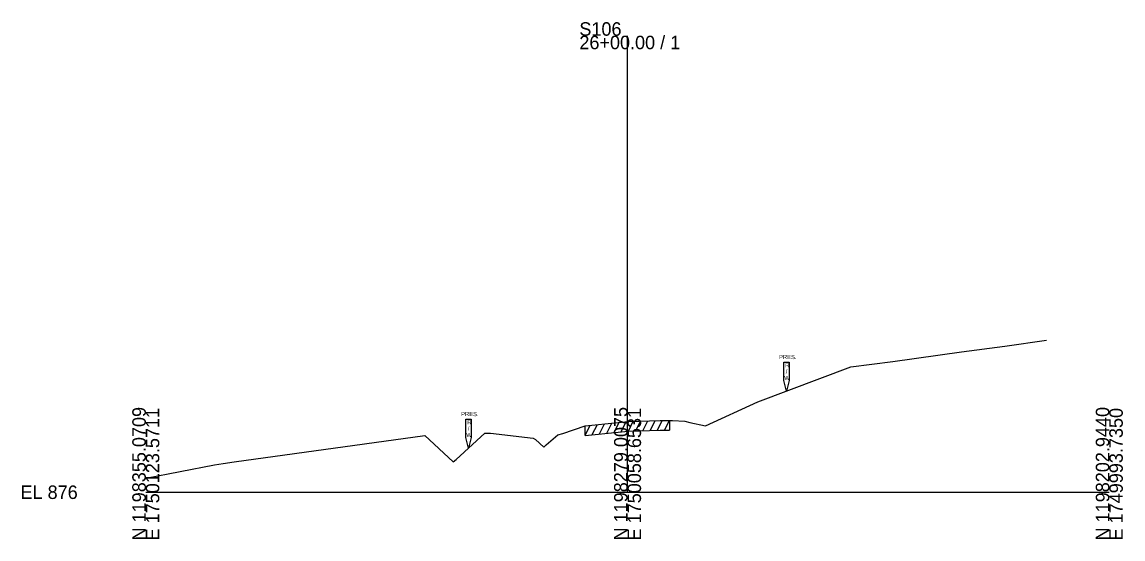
# Model space of a CAD drawing. Extents: x -26 to 1203, y -10 to 19527.
# Drawn here: x -25.7 to 202.8, y 1990.3 to 2097.5 of the extents above; entities that cross this region are included whole.
import ezdxf

# ---------------------------------------------------------------- set-up
doc = ezdxf.new("R2010")
doc.units = 0
for name, color, linetype in [('RD_GPK_XS_Cell', 7, 'Continuous'), ('RD_XS_ExGround', 7, 'Continuous'), ('RD_XS_ExPaveRet', 7, 'Continuous'), ('RD_XS_ExRW', 7, 'Continuous'), ('RD_XS_TX_Elev_EX', 7, 'Continuous')]:
    doc.layers.add(name, color=color, linetype=linetype)

msp = doc.modelspace()

# ---------------------------------------------------------------- linework, layer by layer
at = {"layer": 'RD_GPK_XS_Cell'}
for p, q in [((100, 2000), (100, 2094.69)), ((0, 2000), (100, 2000)), ((100, 2000), (200, 2000))]:
    msp.add_line(p, q, dxfattribs=at)
at = {"layer": 'RD_XS_ExGround'}
msp.add_lwpolyline([(0, 2002.9), (14.26, 2005.71), (16.03, 2005.96), (18.31, 2006.28), (57.95, 2011.78), (63.82, 2006.33), (64.43, 2006.79), (70.4, 2012.25), (71.57, 2012.23), (80.43, 2011.23), (80.9, 2010.91), (82.64, 2009.38), (83.14, 2009.83), (85.53, 2011.9), (86.54, 2012.2), (91.19, 2013.8), (98.06, 2014.49), (100.12, 2014.68), (106.74, 2014.86), (108.73, 2014.9), (109.33, 2014.87), (111.9, 2014.73), (112.95, 2014.47), (116.18, 2013.8), (127.04, 2018.72), (146.38, 2026.01), (155.1, 2027.13), (169.33, 2029.15), (178.32, 2030.3), (186.97, 2031.56)], dxfattribs=at)
at = {"layer": 'RD_XS_ExPaveRet'}
for p, q in [((91.19, 2011.8), (92.24, 2013.9)), ((91.19, 2011.8), (91.19, 2013.8)), ((92.69, 2011.95), (93.74, 2014.06)), ((94.19, 2012.1), (95.24, 2014.21)), ((95.69, 2012.25), (96.74, 2014.36)), ((97.19, 2012.41), (98.24, 2014.51)), ((98.69, 2012.55), (99.74, 2014.65)), ((100.19, 2012.68), (101.2, 2014.71)), ((101.69, 2012.73), (102.7, 2014.75)), ((103.19, 2012.77), (104.2, 2014.79)), ((104.69, 2012.81), (105.7, 2014.83)), ((106.19, 2012.85), (107.2, 2014.87)), ((107.69, 2012.88), (108.7, 2014.9)), ((108.73, 2014.9), (108.73, 2012.9)), ((91.19, 2011.8), (98.06, 2012.49)), ((98.06, 2012.49), (100.12, 2012.68)), ((100.12, 2012.68), (106.74, 2012.86)), ((106.74, 2012.86), (108.73, 2012.9))]:
    msp.add_line(p, q, dxfattribs=at)
at = {"layer": 'RD_XS_ExRW'}
for points in [[(132.45, 2026.98), (133.55, 2026.98), (133.55, 2023.15), (133, 2020.97), (132.45, 2023.15)], [(66.45, 2015.15), (67.55, 2015.15), (67.55, 2011.32), (67, 2009.14), (66.45, 2011.32)]]:
    msp.add_lwpolyline(points, close=True, dxfattribs=at)

# ---------------------------------------------------------------- texts
at = {"layer": 'RD_GPK_XS_Cell'}
for s, p in [('S106', (90, 2094.69)), ('26+00.00 / 1', (90, 2091.89)), ('EL 876', (-26, 1998.6))]:
    msp.add_text(s, height=2.8, dxfattribs=at).set_placement(p)
for s, p in [('N 1198355.0709', (0, 1990)), ('E 1750123.5711', (2.8, 1990)), ('N 1198279.0075', (100, 1990)), ('E 1750058.6531', (102.8, 1990)), ('N 1198202.9440', (200, 1990)), ('E 1749993.7350', (202.8, 1990))]:
    msp.add_text(s, height=2.8, rotation=90, dxfattribs=at).set_placement(p)
at = {"layer": 'RD_XS_ExRW'}
for s, p in [('PRES.', (131.45, 2027.61)), ('R', (132.71, 2025.89)), ('/', (132.83, 2024.58)), ('W', (132.53, 2023.27)), ('PRES.', (65.45, 2015.78)), ('R', (66.71, 2014.06)), ('/', (66.83, 2012.75)), ('W', (66.53, 2011.44))]:
    msp.add_text(s, height=0.875, dxfattribs=at).set_placement(p)
at = {"layer": 'RD_XS_TX_Elev_EX'}
msp.add_text('883.34', height=0.0975, rotation=90, dxfattribs=at).set_placement((100.1, 2014.67))

doc.saveas('drawing.dxf')
